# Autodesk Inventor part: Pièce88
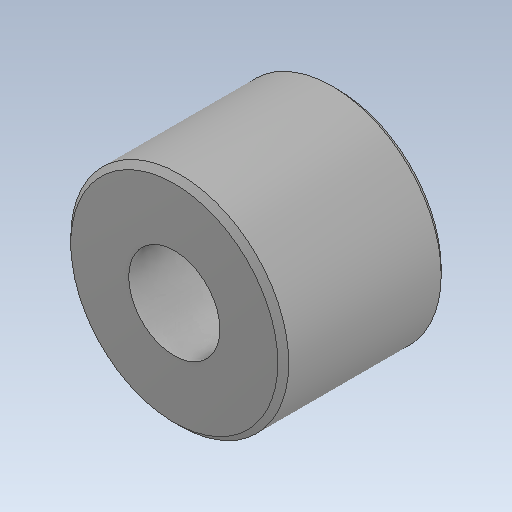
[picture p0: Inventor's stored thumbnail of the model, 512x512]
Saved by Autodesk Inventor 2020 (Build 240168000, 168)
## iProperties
Created: 2022-10
Part Number: Pièce88
Material: Générique
Document SubType Name: Modeling
Designer: bruno
Density: 1 g/cm^3
Appearance: Par défaut
Author: bruno
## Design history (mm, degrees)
feature "Base1"
node "Solide1"
